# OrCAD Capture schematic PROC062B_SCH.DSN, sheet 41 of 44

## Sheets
41 41. SoC POWER SUPPLY: size C; title: SoC POWER SUPPLY
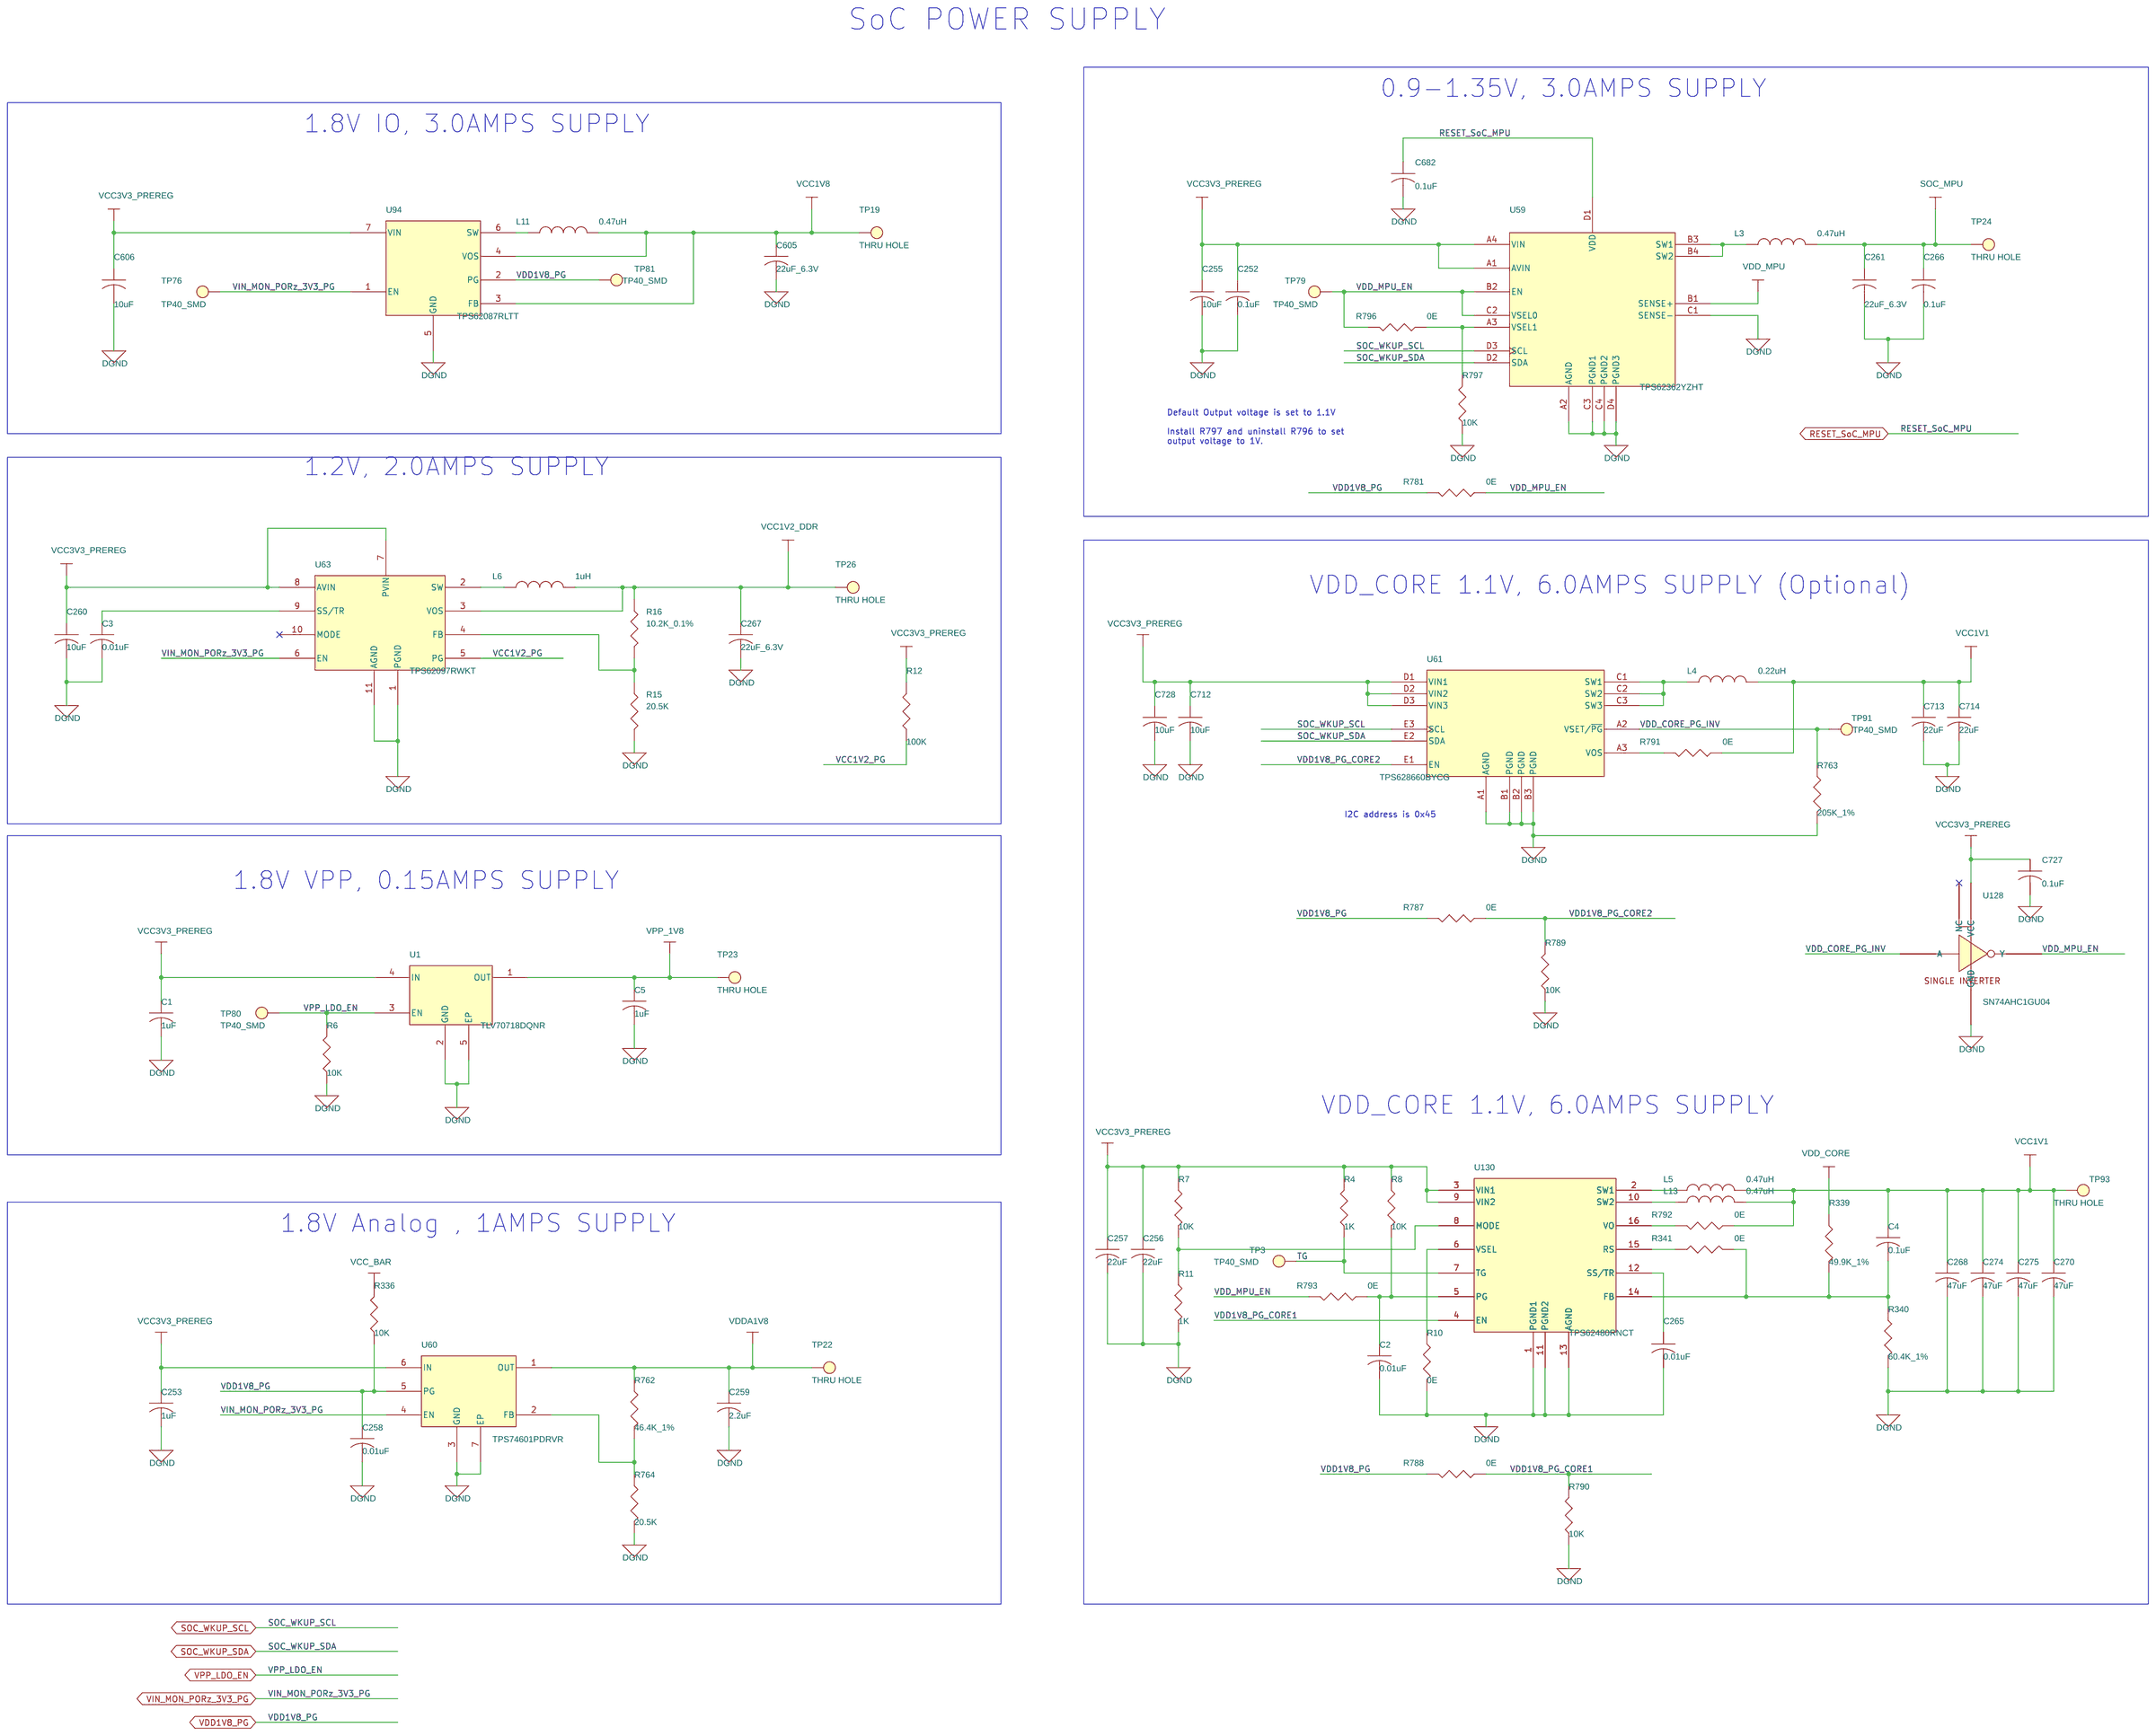
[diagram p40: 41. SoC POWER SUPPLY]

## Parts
C1  1uF  [CAP0603_1]
C2  0.01uF  [CAP0201_0-5]
C3  0.01uF  [CAP0201_0-5]
C4  0.1uF  [CAP0201_0-5]
C5  1uF  [CAP0603_1]
C252  0.1uF  [CAP0201_0-5]
C253  1uF  [CAP0603_1]
C255  10uF  [CAP1206_2]
C256  22uF  [CAP1206_2]
C257  22uF  [CAP1206_2]
C258  0.01uF  [CAP0201_0-5]
C259  2.2uF  [CAP0402_0-75]
C260  10uF  [CAP0603_1]
C261  22uF_6.3V  [CAP0603]
C265  0.01uF  [CAP0402_0-75]
C266  0.1uF  [CAP0201_0-5]
C267  22uF_6.3V  [CAP0603]
C268  47uF  [CAP0603_1]
C270  47uF  [CAP0603_1]
C274  47uF  [CAP0603_1]
C275  47uF  [CAP0603_1]
C605  22uF_6.3V  [CAP0603]
C606  10uF  [CAP1206_2]
C682  0.1uF  [CAP0201_0-5]
C712  10uF  [CAP0603_1]
C713  22uF  [CAP1206_2]
C714  22uF  [CAP1206_2]
C727  0.1uF  [CAP0201_0-5]
C728  10uF  [CAP0603_1]
L3  0.47uH  [IND_XEL4030_170X170_SMD_1-6]
L4  0.22uH  [IND_XAL4020_170X170_SMD_2-1]
L5  0.47uH  [IND_XEL4030_170X170_SMD_1-6]
L6  1uH  [IND_IHLP2020AB_210X210_SMD_1-2]
L11  0.47uH  [IND_XEL4030_170X170_SMD_1-6]
L13  0.47uH  [IND_XEL4030_170X170_SMD_1-6]
R4  1K  [RES0201]
R6  10K  [RES0402_0-5]
R7  10K  [RES0402_0-5]
R8  10K  [RES0402_0-5]
R10  0E  [RES0402_0-5]
R11  1K  [RES0201]
R12  100K  [RES0402_0-5]
R15  20.5K  [RES0402]
R16  10.2K_0.1%  [RES0402]
R336  10K  [RES0402_0-5]
R339  49.9K_1%  [RES0402]
R340  60.4K_1%  [RES0402_0-5]
R341  0E  [RES0402_0-5]
R762  46.4K_1%  [RES0402]
R763  205K_1%  [RES0402_0-5]
R764  20.5K  [RES0402]
R781  0E  [RES0402_0-5]
R787  0E  [RES0402_0-5]
R788  0E  [RES0402_0-5]
R789  10K  [RES0402_0-5]
R790  10K  [RES0402_0-5]
R791  0E  [RES0402_0-5]
R792  0E  [RES0402_0-5]
R793  0E  [RES0402_0-5]
R796  0E  [RES0402_0-5]
R797  10K  [RES0402_0-5]
TP3  TP40_SMD  [TP40_SMD]
TP19  THRU HOLE  [TP_40X65]
TP22  THRU HOLE  [TP_40X65]
TP23  THRU HOLE  [TP_40X65]
TP24  THRU HOLE  [TP_40X65]
TP26  THRU HOLE  [TP_40X65]
TP76  TP40_SMD  [TP40_SMD]
TP79  TP40_SMD  [TP40_SMD]
TP80  TP40_SMD  [TP40_SMD]
TP81  TP40_SMD  [TP40_SMD]
TP91  TP40_SMD  [TP40_SMD]
TP93  THRU HOLE  [TP_40X65]
U1  TLV70718DQNR  [X2SON4_TLV71318P_40X40_0-4]
U59  TPS62362YZHT  [DSBGA16_19-68_80X80_0-7]
U60  TPS74601PDRVR  [SON6_25-59_85X85_0-8]
U61  TPS628660BYCG  [WCSP15_13-77_40X70_0-5]
U63  TPS62097RWKT  [VQFNHR11_TPS62097_80X80_1]
U94  TPS62087RLTT  [VSONHR7_TPS62085_80X80_1]
U128  SN74AHC1GU04  [SOT23-5]
U130  TPS62480RNCT  [VQFNHR16_TPS62480_100X120_1]

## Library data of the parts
C1 C5 C253 = CAP: CAP CERAMIC 1uF 25V 10% X5R 0603; Chkd/date: MANIRAJA/230118; Crtd /date: MANIRAJA/230118; Custom_Duty: 15%; Customs_HS_Code: 85322990; Distributor_name: DIGIKEY; Distributor_part_number: 478-5142-1-ND; Height: 0.94MM; Mfr_name: AVX CORPORATION; Mfr_part_number: 06033D105KAT2A; Mistral Part No: 120010080040-R; Package: 0603; Part_type: CAPACITORS\CERAMIC; Project: TI_MAXIE_CPB; RoHS: RoHS; Temperature: -55°C+85°C; Tolerance: 10%; Voltage: 25V; Wattage: NA; Weight: 2mg; Datasheet: Y:\MIS_DATABASE\DATASHEETS\CAPACITORS\AVX_MLC.PDF
C2 C3 C258 = CAP: CAP CERAMIC 0.01uF 25V 10% X5R 0201; Chkd/date: MANIRAJA/230118; Crtd /date: MANIRAJA/230118; Custom_Duty: 15%; Customs_HS_Code: 85322990; Distributor_name: DIGIKEY; Distributor_part_number: GRM033R61E103KA12J-ND; Height: 0.33MM; Mfr_name: MURATA; Mfr_part_number: GRM033R61E103KA12J; Mistral Part No: 120018010007-R; Package: 0201; Part_type: CAPACITORS\CERAMIC; Project: TI_MAXIE_CPB; RoHS: RoHS; Temperature: -55°C+85°C; Tolerance: 10%; Voltage: 25V; Wattage: NA; Weight: 0.33mg; Datasheet: Y:\MIS_DATABASE\DATASHEETS\CAPACITORS\GRM033R61E103KA12.PDF
C4 C252 C266 C682 C727 = CAP: CAP CERAMIC 0.1uF 16V 10% X5R 0201; Chkd/date: MANIRAJA/120218; Crtd /date: MANIRAJA/120218; Custom_Duty: 15%; Customs_HS_Code: 85322990; Distributor_name: DIGIKEY; Distributor_part_number: 490-16742-1-ND; Height: 0.33MM; Mfr_name: MURATA; Mfr_part_number: GRM033R61C104KE84J; Mistral Part No: 120009030072-R; Package: 0201; Part_type: CAPACITORS\CERAMIC; Project: TI_MAXIE_CPB; RoHS: RoHS; Temperature: -55°C+85°C; Tolerance: 10%; Voltage: 16V; Wattage: NA; Weight: 0.33mg; Datasheet: Y:\MIS_DATABASE\DATASHEETS\CAPACITORS\GRM033R61C104KE84.PDF
C255 = CAP: CAP CERAMIC 10uF 50V 10% X5R 1206; Chkd/date: VASANTHA/190814; Crtd /date: BAVISH/230611; Custom_Duty: 15%; Customs_HS_Code: 85322990; Distributor_name: DIGIKEY; Distributor_part_number: 445-5998-1-ND; Footprint Path: Y:\MIS_DATABASE\Library\ALTIUM_TOOL\PCB_FOOTPRINTS\Altium_Footprint_Lib.PcbLib; Height: 1.90MM; Library Path: Y:\MIS_DATABASE\Library\ALTIUM_TOOL\SCHEMATICS_PARTS\MS_DISCRETE_Library.schlib; Mfr_name: TDK CORPORATION; Mfr_part_number: C3216X5R1H106K160AB; Mistral Part No: 120016030005-R; Package: 1206; Part_type: CAPACITORS\CERAMIC; Project: ITS-SINGAL_COND_CARD; RoHS: RoHS; Temperature: -55°C+85°C; Tolerance: 10%; Voltage: 50V; Wattage: NA; Weight: 16.2mg; Datasheet: Y:\MIS_DATABASE\DATASHEETS\CAPACITORS\TDK_C-SER-JUL17.PDF
C256 C257 C713 C714 = CAP: CAP CERAMIC 22uF 16V 20% X7R 1206; Chkd/date: VASANTHA/170117; Crtd /date: VASANTHA/170117; Custom_Duty: 15%; Customs_HS_Code: 85322990; Distributor_name: DIGIKEY; Distributor_part_number: 587-4319-1-ND; Height: 1.90MM; Mfr_name: TAIYO YUDEN; Mfr_part_number: EMK316BB7226ML-T; Mistral Part No: 120017010003-R; Package: 1206; Part_type: CAPACITORS\CERAMIC; Project: TRMM_SMART-M_PS; RoHS: RoHS; Temperature: -55°C+125°C; Tolerance: 20%; Voltage: 16V; Wattage: NA; Weight: 16.2mg; Datasheet: Y:\MIS_DATABASE\DATASHEETS\CAPACITORS\EMK316BB7226ML.PDF
C259 = CAP: CAP CERAMIC 2.2uF 10V 20% X5R 0402; Chkd/date: MANIRAJA/240118; Crtd /date: MANIRAJA/240118; Custom_Duty: 15%; Customs_HS_Code: 85322990; Distributor_name: DIGIKEY; Distributor_part_number: 490-12254-1-ND; Height: 0.55MM; Mfr_name: MURATA; Mfr_part_number: GRT155R61A225ME01D; Mistral Part No: 120018010016-R; Package: 0402; Part_type: CAPACITORS\CERAMIC; Project: TI_MAXIE_CPB; RoHS: RoHS; Temperature: -55°C+85°C; Tolerance: 20%; Voltage: 10V; Wattage: NA; Weight: 0.65mg; Datasheet: Y:\MIS_DATABASE\DATASHEETS\CAPACITORS\GRT155R61A225ME01.PDF
C260 C712 C728 = CAP: CAP CERAMIC 10uF 10V 10% X5R 0603; Chkd/date: MANIRAJA/230118; Crtd /date: MANIRAJA/230118; Custom_Duty: 15%; Customs_HS_Code: 85322990; Distributor_name: DIGIKEY; Distributor_part_number: 478-10766-1-ND; Height: 0.94MM; Mfr_name: AVX CORPORATION; Mfr_part_number: 0603ZD106KAT2A; Mistral Part No: 120010080001-R; Package: 0603; Part_type: CAPACITORS\CERAMIC; Project: TI_MAXIE_CPB; RoHS: RoHS; Temperature: -55°C+85°C; Tolerance: 10%; Voltage: 10V; Wattage: NA; Weight: 2mg; Datasheet: Y:\MIS_DATABASE\DATASHEETS\CAPACITORS\AVX_MLC.PDF
C261 C267 C605 = CAP: CAP CERAMIC 22uF 6.3V 20% X5R 0603; Alternate_mfr_name_A: YAGEO AMERICA; Alternate_mfr_part_number_A: CC0603MRX5R5BB226; Chkd/date: JEBRAN/090915; Crtd /date: JEBRAN/090915; Custom_Duty: 15%; Customs_HS_Code: 85322990; Distributor_name: DIGIKEY; Distributor_name_A: DIGIKEY; Distributor_part_number: 490-7611-2-ND; Distributor_part_number_A: 311-1815-1-ND; Height: 1.00MM; Mfr_name: MURATA; Mfr_part_number: GRM188R60J226MEA0; Mistral Part No: 120015090007-R; Package: 0603; Part_type: CAPACITORS\CERAMIC; Project: OCTBTS_3000; RoHS: RoHS; Temperature: -55°C+85°C; Tolerance: 20%; Voltage: 6.3V; Wattage: NA; Weight: NA; Datasheet: Y:\MIS_DATABASE\DATASHEETS\CAPACITORS\GRM188SERIES.PDF
C265 = CAP: CAP CERAMIC 0.01uF 10V 10% X7R 0402; Chkd/date: VASANTHA/061216; Crtd /date: MAZHAR/201005; Custom_Duty: 15%; Customs_HS_Code: 85322990; Distributor_name: DIGIKEY; Distributor_part_number: 478-7890-1-ND; Height: 0.56MM; Mfr_name: AVX CORPORATION; Mfr_part_number: 0402ZC103KAT2A; Mistral Part No: 120009030017-R; Package: 0402; Part_type: CAPACITORS\CERAMIC; Project: ADR; RoHS: RoHS; Temperature: -55°C+125°C; Tolerance: 10%; Voltage: 10V; Wattage: NA; Weight: 0.65mg; Datasheet: Y:\MIS_DATABASE\DATASHEETS\CAPACITORS\AVX_MLC.PDF
C268 C270 C274 C275 = CAP: CAP CERAMIC 47uF 6.3V 20% X5R 0603; Chkd/date: VASANTHA/211116; Crtd /date: MANIRAJA/211116; Custom_Duty: 15%; Customs_HS_Code: 85322990; Distributor_name: DIGIKEY; Distributor_part_number: 490-13247-1-ND; Height: 0.90MM; Mfr_name: MURATA; Mfr_part_number: GRM188R60J476ME15D; Mistral Part No: 120016110001-R; Package: 0603; Part_type: CAPACITORS\CERAMIC; Project: DLRL_3U_ESM_VPX; RoHS: RoHS; Temperature: -55°C+85°C; Tolerance: 20%; Voltage: 6.3V; Wattage: NA; Weight: 9.10mg; Datasheet: Y:\MIS_DATABASE\DATASHEETS\CAPACITORS\GRM188SERIES.PDF
C606 = CAP: CAP CERAMIC 10uF 16V 10% X7R 1206; Chkd/date: VASANTHA/291216; Crtd /date: MAZHAR/120909; Custom_Duty: 15%; Customs_HS_Code: 85322990; Distributor_name: DIGIKEY; Distributor_part_number: 399-3525-1-ND; Height: 1.80MM; Mfr_name: KEMET; Mfr_part_number: C1206C106K4RACTU; Mistral Part No: 120009090010-R; Package: 1206; Part_type: CAPACITORS\CERAMIC; Project: ADE POWER SUPPLY; RoHS: RoHS; Temperature: -55°C+125°C; Tolerance: 10%; Voltage: 16V; Wattage: NA; Weight: 16.2mg; Datasheet: Y:\MIS_DATABASE\DATASHEETS\CAPACITORS\KEMET-C08_X.PDF
L3 L5 L11 L13 = INDUCTOR: IND POWER 0.47uH 20% 11.2A SMD; Chkd/date: MANIRAJA/150218; Crtd /date: ALVY/150218; Custom_Duty: 24%; Customs_HS_Code: 85437099; Distributor_name: MOUSER; Distributor_part_number: 994-XFL4015-471MEB; Footprint Path: Y:\MIS_DATABASE\Library\ALTIUM_TOOL\PCB_FOOTPRINTS\Altium_Footprint_Lib.PcbLib; Height: 1.60MM; Library Path: Y:\MIS_DATABASE\Library\ALTIUM_TOOL\SCHEMATICS_PARTS\MS_DISCRETE_Library.schlib; Mfr_name: COILCRAFT; Mfr_part_number: XFL4015-471MEB; Mistral Part No: 130018020040-R; Package: SMD; Project: TI_MAXIE_CPB; RoHS: RoHS; Temperature: -40°C+125°C; Tolerance: 20%; Voltage: NA; Wattage: NA; Weight: 95mg; Datasheet: Y:\MIS_DATABASE\DATASHEETS\DISCRETES\INDUCTORS\XFL4015.PDF
L4 = INDUCTOR: IND POWER 0.22uH 16.8A 20% SMD; Chkd/date: MANIRAJA/100619; Crtd /date: MANIRAJA/100619; Custom_Duty: 24%; Customs_HS_Code: 85437099; Distributor_name: MOUSER; Distributor_part_number: 994-XAL4020-221MEB; Footprint Path: Y:\MIS_DATABASE\Library\ALTIUM_TOOL\PCB_FOOTPRINTS\Altium_Footprint_Lib.PcbLib; Height: 2.10MM; Library Path: Y:\MIS_DATABASE\Library\ALTIUM_TOOL\SCHEMATICS_PARTS\MS_DISCRETE_Library.schlib; Mfr_name: COILCARFT; Mfr_part_number: XAL4020-221MEB; Mistral Part No: 130019060012-R; Package: SMD; Project: TI_MAXIE_CPB; RoHS: RoHS; Temperature: -40°C+125°C; Tolerance: 20%; Voltage: NA; Wattage: NA; Weight: 180mg; Datasheet: Y:\MIS_DATABASE\DATASHEETS\DISCRETES\INDUCTORS\XAL40XX.PDF
L6 = INDUCTOR: IND POWER 1uH 4.4A 20% SMD; Chkd/date: VASANTHA/170317; Crtd /date: MANIRAJA/160317; Custom_Duty: 24%; Customs_HS_Code: 85437099; Distributor_name: DIGIKEY; Distributor_part_number: 541-1704-1-ND; Height: 1.20MM; Mfr_name: VISHAY; Mfr_part_number: IHLP2020ABER1R0M01; Mistral Part No: 130017030015-R; Package: SMD; Project: ADA_3U_FMC; RoHS: RoHS; Temperature: -55°C+125°C; Tolerance: 20%; Voltage: NA; Wattage: NA; Weight: 200mg; Datasheet: Y:\MIS_DATABASE\DATASHEETS\DISCRETES\INDUCTORS\IHLP2020AB.PDF
R4 R11 = RESISTOR: RES 1K 1/20W 5% 0201; Chkd/date: JEBRAN/110815; Crtd /date: JEBRAN/110815; Custom_Duty: 15%; Customs_HS_Code: 85332119; Distributor_name: DIGIKEY; Distributor_part_number: 541-1.00KAABCT-ND; Height: 0.28MM; Mfr_name: VISHAY; Mfr_part_number: CRCW02011K00FKED; Mistral Part No: 110015080014-R; Package: 0201; Part_type: RESISTORS\FIXED; Project: OCTASIC_3000; RoHS: RoHS; Temperature: -55°C+155°C; Tolerance: 5%; Voltage: NA; Wattage: 1/20W; Weight: NA; Datasheet: Y:\MIS_DATABASE\DATASHEETS\RESISTORS\CRCW0201.PDF
R6-R8 R336 R789 R790 R797 = RESISTOR: RES 10K 1/16W 5% 0402; Chkd/date: VASANTHA/061216; Crtd /date: MAZHAR/230805; Custom_Duty: 15%; Customs_HS_Code: 85332119; Distributor_name: DIGIKEY; Distributor_part_number: 311-10KJRCT-ND; Footprint Path: Y:\MIS_DATABASE\Library\ALTIUM_TOOL\PCB_FOOTPRINTS\Altium_Footprint_Lib.PcbLib; Height: 0.40MM; Library Path: Y:\MIS_DATABASE\Library\ALTIUM_TOOL\SCHEMATICS_PARTS\MS_DISCRETE_Library.schlib; Mfr_name: YAGEO AMERICA; Mfr_part_number: RC0402JR-0710KL; Mistral Part No: 110009030208-R; Package: 0402; Part_type: RESISTORS\FIXED; Project: HSE; RoHS: Pb-Free; Temperature: -55°C+155°C; Tolerance: 5%; Voltage: NA; Wattage: 1/16W; Weight: 0.65mg; Datasheet: Y:\MIS_DATABASE\DATASHEETS\RESISTORS\YAGEO-RC0402.PDF
R10 R341 R781 R787 R788 R791-R793 R796 = RESISTOR: RES 0E 1/16W 0402; Chkd/date: VASANTHA/201216; Crtd /date: MUDDU/190810; Custom_Duty: 15%; Customs_HS_Code: 85332119; Distributor_name: DIGIKEY; Distributor_part_number: 541-0.0JCT-ND; Footprint Path: Y:\MIS_DATABASE\Library\ALTIUM_TOOL\PCB_FOOTPRINTS\Altium_Footprint_Lib.PcbLib; Height: 0.40MM; Library Path: Y:\MIS_DATABASE\Library\ALTIUM_TOOL\SCHEMATICS_PARTS\MS_DISCRETE_Library.schlib; Mfr_name: VISHAY; Mfr_part_number: CRCW04020000Z0ED; Mistral Part No: 110010080019-P; Package: 0402; Part_type: RESISTORS\FIXED; Project: PB_BUGBASE; RoHS: Pb-Free; Temperature: -55°C+155°C; Tolerance: NA; Voltage: NA; Wattage: 1/16W; Weight: 0.65g/1000pcs; Datasheet: Y:\MIS_DATABASE\DATASHEETS\RESISTORS\CRCW0603.PDF
R12 = RESISTOR: RES 100K 1/16W 5% 0402; Chkd/date: VASANTHA/061216; Crtd /date: BAVISH/010611; Custom_Duty: 15%; Customs_HS_Code: 85332119; Distributor_name: DIGIKEY; Distributor_part_number: 541-100KJCT-ND; Height: 0.40MM; Mfr_name: VISHAY; Mfr_part_number: CRCW0402100KJNED; Mistral Part No: 110011060002-R; Package: 0402; Part_type: RESISTORS\FIXED; Project: AM4515_EVM_LCD; RoHS: RoHS; Temperature: -55°C+155°C; Tolerance: 5%; Voltage: NA; Wattage: 1/16W; Weight: 0.65mg; Datasheet: Y:\MIS_DATABASE\DATASHEETS\RESISTORS\CRCW0603.PDF
R15 R764 = RESISTOR: RES 20.5K 1/10W 1% 0402; Chkd/date: MAZHAR/0141010; Crtd /date: BAVISH/290910; Custom_Duty: 15%; Customs_HS_Code: 85332119; Distributor_name: DIGIKEY; Distributor_part_number: P20.5KLCT-ND; Footprint Path: Y:\MIS_DATABASE\Library\ALTIUM_TOOL\PCB_FOOTPRINTS\Altium_Footprint_Lib.PcbLib; Height: 0.40MM; Library Path: Y:\MIS_DATABASE\Library\ALTIUM_TOOL\SCHEMATICS_PARTS\MS_DISCRETE_Library.schlib; Mfr_name: PANASONIC-ECG; Mfr_part_number: ERJ-2RKF2052X; Mistral Part No: 110010090063-R; Package: 0402; Part_type: RESISTORS\FIXED; Project: ITS; RoHS: RoHS; Temperature: -55°C+125°C; Tolerance: 1%; Wattage: 1/10W; Weight: 0.8/1000g; Datasheet: Y:\MIS_DATABASE\DATASHEETS\RESISTORS\ERJ2R.PDF
R16 = RESISTOR: RES 10.2K 1/16W 0.1% 0402; Chkd/date: MAZHAR/200611; Crtd /date: BAVISH/240511; Custom_Duty: 15%; Customs_HS_Code: 85332119; Distributor_name: DIGIKEY; Distributor_part_number: TNP10.2KDACT-ND; Height: 0.40MM; Mfr_name: VISHAY; Mfr_part_number: TNPW040210K2BEED; Mistral Part No: 110011050017-R; Package: 0402; Part_type: RESISTORS\FIXED; Project: HMC; RoHS: RoHS; Temperature: -55°C+125°C; Tolerance: 0.1%; Voltage: NA; Wattage: 1/16W; Weight: 0.65/1000g; Datasheet: Y:\MIS_DATABASE\DATASHEETS\RESISTORS\VISHAY_TNPW.PDF
R339 = RESISTOR: RES 49.9K1/16W 1% 0402; Chkd/date: MAZHAR/220709; Crtd /date: GEETHA/090606; Custom_Duty: 15%; Customs_HS_Code: 85332119; Distributor_name: DIGIKEY; Distributor_part_number: 311-49.9KLRCT-ND; Height: 0.40MM; Mfr_name: YAGEO AMERICA; Mfr_part_number: RC0402FR-0749K9L; Mistral Part No: 110009030904-P; Package: 0402; Part_type: RESISTORS\FIXED; Project: PNAV; RoHS: Pb-Free; Tolerance: 1%; Wattage: 1/16W; Datasheet: Y:\MIS_DATABASE\DATASHEETS\RESISTORS\YAGEO-RC0402.PDF
R340 = RESISTOR: RES 60.4K 1/16W 1% 0402; Chkd/date: VASANTHA/281216; Crtd /date: USMAN/201112; Cust_part_number: 4700-80042E; Custom_Duty: 15%; Customs_HS_Code: 85332119; Distributor_name: DIGIKEY; Distributor_part_number: 311-60.4KLRCT-ND; Height: 0.40MM; Mfr_name: YAGEO AMERICA; Mfr_part_number: RC0402FR-0760K4L; Mistral Part No: 110012110012-R; Package: 0402; Part_type: RESISTORS\FIXED; Project: ITS-CONTROLER_CARD; RoHS: RoHS; Temperature: -55°C+155°C; Tolerance: 1%; Voltage: NA; Wattage: 1/16W; Weight: 0.65mg; Datasheet: Y:\MIS_DATABASE\DATASHEETS\RESISTORS\YAGEO-RC0402.PDF
R762 = RESISTOR: RES 46.4K 1/16W 1% 0402; Chkd/date: USMAN/230413; Crtd /date: USMAN/180213; Custom_Duty: 15%; Customs_HS_Code: 85332119; Distributor_name: DIGIKEY; Distributor_part_number: 541-46.4KLCT-ND; Footprint Path: Y:\MIS_DATABASE\Library\ALTIUM_TOOL\PCB_FOOTPRINTS\Altium_Footprint_Lib.PcbLib; Height: 0.40MM; Library Path: Y:\MIS_DATABASE\Library\ALTIUM_TOOL\SCHEMATICS_PARTS\MS_DISCRETE_Library.schlib; Mfr_name: VISHAY; Mfr_part_number: CRCW040246K4FKED; Mistral Part No: 110013020001-R; Package: 0402; Part_type: RESISTORS\FIXED; Project: ITS-SCP; RoHS: RoHS; Temperature: -55°C+155°C; Tolerance: 1%; Voltage: NA; Wattage: 1/16W; Weight: 0.65mg; Datasheet: Y:\MIS_DATABASE\DATASHEETS\RESISTORS\CRCW0603.PDF
R763 = RESISTOR: RES 205K 1/10W 1% 0402; Chkd/date: MAZHAR/110310; Crtd /date: MUDDU/080310; Custom_Duty: 15%; Customs_HS_Code: 85332119; Distributor_name: DIGIKEY; Distributor_part_number: P205KLCT-ND; Footprint Path: Y:\MIS_DATABASE\Library\ALTIUM_TOOL\PCB_FOOTPRINTS\Altium_Footprint_Lib.PcbLib; Height: 0.40MM; Library Path: Y:\MIS_DATABASE\Library\ALTIUM_TOOL\SCHEMATICS_PARTS\MS_DISCRETE_Library.schlib; Mfr_name: PANASONIC-ECG; Mfr_part_number: ERJ-2RKF2053X; Mistral Part No: 110010030029-R; Package: 0402; Part_type: RESISTORS\FIXED; Project: VME_DSP_SUITE; RoHS: RoHS; Temperature: -55°C+155°C; Tolerance: 1%; Voltage: NA; Wattage: 1/10W; Weight: 0.8mg; Datasheet: Y:\MIS_DATABASE\DATASHEETS\RESISTORS\PAN-ERJSER_NOV17.PDF
TP3 TP76 TP79-TP81 TP91 = TESTPOINT: TESTPOINT CIR 40 SMD; Chkd/date: MAZHAR/190505; Crtd /date: MAZHAR/190505; Distributor_name: NA; Distributor_part_number: NA; Footprint Path: Y:\MIS_DATABASE\Library\ALTIUM_TOOL\PCB_FOOTPRINTS\Altium_Footprint_Lib.PcbLib; Height: NA; Library Path: Y:\MIS_DATABASE\Library\ALTIUM_TOOL\SCHEMATICS_PARTS\MS_DISCRETE_Library.schlib; MECHANICAL 3D STEP FILE: NA; Mfr_name: LOCAL; Mistral Part No: 130009030933; Package: SMD; Project: RAINIER-3; RoHS: NA; Temperature: NA; Tolerance: NA; Voltage: NA; Wattage: NA; Weight: NA; Datasheet: NA
TP19 TP22-TP24 TP26 TP93 = TESTPOINT: TESTPOINT 1.0MM DRILL PTH; Chkd/date: MAZHAR/271211; Crtd /date: SHREESHAIL/041005; Distributor_name: NA; Distributor_part_number: NA; Height: NA; Mfr_name: LOCAL; Mistral Part No: 130009030938; Package: THRU-HOLE; Part_type: MISC\TESTPOINT; Project: HSE; Datasheet: NA
U1 = TLV71318PDQNR_X2SON4: IC 200mA LOW IQ LOW NOISE LDO REGULATOR X2SON-4; Chkd/date: MANIRAJA/270218; Crtd /date: ALVY/260218; Custom_Duty: 15%; Customs_HS_Code: 85423100; Distributor_name: DIGIKEY; Distributor_part_number: 296-36768-1-ND; Footprint Path: Y:\MIS_DATABASE\Library\ALTIUM_TOOL\PCB_FOOTPRINTS\Altium_Footprint_Lib.PcbLib; Height: 0.40MM; Library Path: Y:\MIS_DATABASE\Library\ALTIUM_TOOL\SCHEMATICS_PARTS\MS_MISCPOWER_Library.schlib; Mfr_name: TEXAS INSTRUMENTS; Mistral Part No: 142018020038-R; Package: X2SON-4; Part_type: ICS\POWER\VOLTAGE REGULATOR; Project: TI_MAXIE_CPB; RoHS: RoHS; Temperature: -40°C+125°C; Tolerance: NA; Voltage: NA; Wattage: NA; Weight: 1.5mg; Datasheet: Y:\MIS_DATABASE\DATASHEETS\ICS\POWER\TLV707X.PDF
U59 = TPS6236X_DSBGA16: IC 3A PROCESSOR SUPPLY WITH I2C INTERFACE AND REMOTE SENSE DSBGA16; Chkd/date: MANIRAJA/090120; Crtd /date: ALVY/090120; Custom_Duty: 15%; Customs_HS_Code: 85423100; Distributor_name: DIGIKEY; Distributor_part_number: 296-TPS62362YZHTCT-ND; Footprint Path: Y:\MIS_DATABASE\Library\ALTIUM_TOOL\PCB_FOOTPRINTS\Altium_Footprint_Lib.PcbLib; Height: 0.63MM; Library Path: Y:\MIS_DATABASE\Library\ALTIUM_TOOL\SCHEMATICS_PARTS\MS_MISCPOWER_Library.schlib; Mfr_name: TEXAS INSTRUMENTS; Mistral Part No: 142020010003-R; Package: DSBGA16; Part_type: ICS\POWER\DC-DC CONVERTER; Project: TI_MAXIE_CPB; RoHS: RoHS; Temperature: -40°C+85°C; Tolerance: NA; Voltage: NA; Wattage: NA; Weight: 5.1mg; Datasheet: Y:\MIS_DATABASE\DATASHEETS\ICS\POWER\TPS6236XX.PDF
U60 = TPS74501_WSON6: IC 1A ADJ OUTPUT LDO WITH POWER-GOOD WSON6; Chkd/date: MANIRAJA/060619; Crtd /date: ALVY/060619; Custom_Duty: 15%; Customs_HS_Code: 85423100; Distributor_name: MOUSER; Distributor_part_number: 595-TPS74601PDRVR; Footprint Path: Y:\MIS_DATABASE\Library\ALTIUM_TOOL\PCB_FOOTPRINTS\Altium_Footprint_Lib.PcbLib; Height: 0.80MM; Library Path: Y:\MIS_DATABASE\Library\ALTIUM_TOOL\SCHEMATICS_PARTS\MS_MISCPOWER_Library.schlib; Mfr_name: TEXAS INSTRUMENTS; Mistral Part No: 142019060004-R; Package: WSON6; Part_type: ICS\POWER\VOLTAGE REGULATOR; Project: TI_MAXIE_CPB; RoHS: RoHS; Temperature: -40°C+125°C; Tolerance: NA; Voltage: NA; Wattage: NA; Weight: NA; Datasheet: Y:\MIS_DATABASE\DATASHEETS\ICS\POWER\TPS74601.PDF
U61 = TPS628660B_WCSP15: IC 2.4-5.5V I/P 6A O/P SYNC STEP DOWN CONVERTER WITH I2C INTERFACE WCSP15; Chkd/date: MANIRAJA/040619; Crtd /date: MANIRAJA/040619; Custom_Duty: 15%; Customs_HS_Code: 85423100; Distributor_name: NA; Distributor_part_number: NA; Footprint Path: Y:\MIS_DATABASE\Library\ALTIUM_TOOL\PCB_FOOTPRINTS\Altium_Footprint_Lib.PcbLib; Height: 0.50MM; Library Path: Y:\MIS_DATABASE\Library\ALTIUM_TOOL\SCHEMATICS_PARTS\MS_MISCPOWER_Library.schlib; Mfr_name: TEXAS INSTRUMENTS; Mistral Part No: 142019060001; Package: WCSP15; Part_type: ICS\POWER\CONVERTER; Project: TI_MAXIE_CPB; RoHS: NA; Temperature: NA; Tolerance: NA; Voltage: NA; Wattage: NA; Weight: NA; Datasheet: Y:\MIS_DATABASE\DATASHEETS\ICS\POWER\TPS62866.PDF
U63 = TPS62097RWKT_VQFNHR11: IC 2A SYNCHRONOUS STEP DOWN CONVERTER WITH IDCS CONTROL VQFN-HR11; Chkd/date: MANIRAJA/270917; Crtd /date: MANIRAJA/270917; Custom_Duty: 15%; Customs_HS_Code: 85423100; Distributor_name: DIGIKEY; Distributor_part_number: 296-43330-1-ND; Height: 1.00MM; Mfr_name: TEXAS INSTRUMENTS; Mistral Part No: 142017090025-R; Package: VQFN-HR11; Part_type: ICS\POWER\CONVERTER; Project: TI_MAXIE_CPB; RoHS: RoHS; Temperature: -40°C+125°C; Tolerance: NA; Voltage: NA; Wattage: NA; Weight: NA; Datasheet: Y:\MIS_DATABASE\DATASHEETS\ICS\POWER\TPS62097.PDF
U94 = TPS62085RLTR_VSONHR7: IC 3A 1.8V STEP DOWN CONVERTER WITH SHORT CIRCUIT PROTECTION VSON-HR7; Chkd/date: MANIRAJA/310818; Crtd /date: MANIRAJA/310818; Custom_Duty: 15%; Customs_HS_Code: 85423100; Distributor_name: DIGIKEY; Distributor_part_number: 296-37087-1-ND; Footprint Path: Y:\MIS_DATABASE\Library\ALTIUM_TOOL\PCB_FOOTPRINTS\Altium_Footprint_Lib.PcbLib; Height: 1.00MM; Library Path: Y:\MIS_DATABASE\Library\ALTIUM_TOOL\SCHEMATICS_PARTS\MS_MISCPOWER_Library.schlib; Mfr_name: TEXAS INSTRUMENTS; Mistral Part No: 142018080020-R; Package: VSON-HR7; Part_type: ICS\POWER\CONVERTER; Project: TI_MAXIE_CPB; RoHS: RoHS; Temperature: -40°C+125°C; Tolerance: NA; Voltage: NA; Wattage: NA; Weight: 8.8mg; Datasheet: Y:\MIS_DATABASE\DATASHEETS\ICS\POWER\TPS62085.PDF
U128 = SN74AHC1GU04DBVR_SOT23-5: IC SINGLE INVERTER GATE SOT23-5; Chkd/date: SHREESHAIL/120106; Crtd /date: MAZHAR/160805; Custom_Duty: 15%; Customs_HS_Code: 85423100; Distributor_name: DIGIKEY; Distributor_part_number: 296-1095-1-ND; Height: 1.45MM; Mfr_name: TEXAS INSTRUMENTS; Mfr_part_number: SN74AHC1GU04DBVR; Mistral Part No: 141009030206; Part_type: ICS\DIGITAL\GATES; Project: HSE; Datasheet: Y:\MIS_DATABASE\DATASHEETS\ICS\DIGITAL\GATES\SN74AHC1GU04.PDF
U130 = TPS62480RNCT_VQFNHR16: IC 2-PHASE STEP DOWN DC-DC CONVERTER VQFN-HR16; Chkd/date: MANIRAJA/220917; Crtd /date: MANIRAJA/220917; Custom_Duty: 15%; Customs_HS_Code: 85423100; Distributor_name: DIGIKEY; Distributor_part_number: 296-43867-1-ND; Height: 1.00MM; Mfr_name: TEXAS INSTRUMENTS; Mistral Part No: 142017090012-R; Package: VQFN-HR16; Part_type: ICS\POWER\DC-DC CONVERTER; Project: TI_MAXIE_CPB; RoHS: RoHS; Temperature: -40°C+125°C; Tolerance: NA; Voltage: NA; Wattage: NA; Weight: 46mg; Datasheet: Y:\MIS_DATABASE\DATASHEETS\ICS\POWER\TPS62480R.PDF

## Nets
DGND: C1.2 C2.2 C3.2 C5.2 C252.2 C253.2 C255.2 C256.2 C257.2 C258.2 C259.2 C260.2 C261.2 C265.2 C266.2 C267.2 C268.2 C270.2 C274.2 C275.2 C605.2 C606.2 C682.2 C712.2 C713.2 C714.2 C727.2 C728.2 R6.1 R10.2 R11.2 R15.2 R340.2 R763.2 R764.2 R789.1 R790.1 R797.1 U1.2(GND) U1.5(EP) U59.A2(AGND) U59.C1(SENSE-) U59.C3(PGND1) U59.C4(PGND2) U59.D4(PGND3) U60.3(GND) U60.7(EP) U61.A1(AGND) U61.B1(PGND) U61.B2(PGND) U61.B3(PGND) U63.1(PGND) U63.11(AGND) U94.5(GND) U128.3(GND) U130.1(PGND1) U130.11(PGND2) U130.13(AGND) ; also on sheet 11 12 13 14 15 16 17 18 19 20 21 22 23 24 25 26 27 28 29 30 31 32 33 34 35 36 37 38 39 40 42 43 44
VCC1V1: C4.1 C268.1 C270.1 C274.1 C275.1 C713.1 C714.1 L4.2 L5.2 L13.2 R791.1 R792.1 TP93.1(TP) ; also on sheet 26
VCC1V2_DDR: C267.1 L6.2 R16.1 TP26.1(TP) U63.3(VOS) ; also on sheet 26
VCC1V2_PG: R12.1 U63.5(PG)
VCC1V8: C605.1 L11.2 TP19.1(TP) U94.3(FB) U94.4(VOS) ; also on sheet 11 18 19 20 21 22 23 26 29 31 33 35 36 37 38 44
VCC3V3_IO: R336.2 ; also on sheet 11 18 19 20 21 22 23 24 25 26 28 29 30 31 33 34 35 36 37 38 39 42 43 44
VCC3V3_PREREG: C1.1 C252.1 C253.1 C255.1 C256.1 C257.1 C260.1 C606.1 C712.1 C727.1 C728.1 R4.2 R7.1 R8.1 R12.2 U1.4(IN) U59.A1(AVIN) U59.A4(VIN) U60.6(IN) U61.D1(VIN1) U61.D2(VIN2) U61.D3(VIN3) U63.7(PVIN) U63.8(AVIN) U94.7(VIN) U128.5(VCC) U130.3(VIN1) U130.9(VIN2) ; also on sheet 13 39 40 42
VDD1V8_PG: C258.1 R336.1 R781.2 R787.2 R788.2 TP81.1(TP) U60.5(PG) U94.2(PG) ; also on sheet 42
VDD1V8_PG_CORE1: R788.1 R790.2 U130.4(EN)
VDD1V8_PG_CORE2: R787.1 R789.2 U61.E1(EN)
VDD_CORE: R339.1 ; also on sheet 12 13 26 39
VDD_CORE_PG_INV: R763.1 TP91.1(TP) U61.A2(VSET/~{PG}) U128.2(A)
VDD_MPU: U59.B1(SENSE+) ; also on sheet 12 26 39
VDD_MPU_EN: R781.1 R793.2 R796.2 TP79.1(TP) U59.B2(EN) U59.C2(VSEL0) U128.4(Y)
VDDA1V8: C259.1 R762.1 TP22.1(TP) U60.1(OUT) ; also on sheet 26
VIN_MON_PORz_3V3_PG: TP76.1(TP) U60.4(EN) U63.6(EN) U94.1(EN) ; also on sheet 39 42
RESET_SoC_MPU: C682.1 U59.D1(VDD) ; also on sheet 37
SoC_MPU: C261.1 C266.1 L3.2 TP24.1(TP) ; also on sheet 26
SOC_WKUP_SCL: U59.D3(SCL) U61.E3(SCL) ; also on sheet 20 33 34 35 44
SOC_WKUP_SDA: U59.D2(SDA) U61.E2(SDA) ; also on sheet 20 33 34 35 44
TG: R4.1 TP3.1(TP) U130.7(TG)
VPP_1V8: C5.1 TP23.1(TP) U1.1(OUT) ; also on sheet 13
VPP_LDO_EN: R6.2 TP80.1(TP) U1.3(EN) ; also on sheet 19
N17781485: L11.1 U94.6(SW)
N17781689: L6.1 U63.2(SW)
N17781701: R15.1 R16.2 U63.4(FB)
N17781734: L3.1 U59.B3(SW1) U59.B4(SW2)
N18550089: C3.1 U63.9(SS/TR)
N23079966: R762.2 R764.1 U60.2(FB)
N23093100: L4.1 U61.C1(SW1) U61.C2(SW2) U61.C3(SW3)
N23956430: C265.1 U130.12(SS/TR)
N23956432: C4.2 R339.2 R340.1 R341.2 U130.14(FB)
N23956434: R10.1 U130.6(VSEL)
N23956518: C2.1 R8.2 R793.1 U130.5(PG)
N23956734: R7.2 R11.1 U130.8(MODE)
N23956742: L5.1 U130.2(SW1)
N23956744: L13.1 U130.10(SW2)
N23956762: R792.2 U130.16(VO)
N23956795: R341.1 U130.15(RS)
N24018720: R791.2 U61.A3(VOS)
N24303686: R796.1 R797.2 U59.A3(VSEL1)

Not connected (* = marked no-connect by the designer): U63 10(MODE)*; U128 1(NC)*

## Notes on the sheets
sheet 41
- SoC POWER SUPPLY
- 0.9-1.35V, 3.0AMPS SUPPLY
- 1.8V IO, 3.0AMPS SUPPLY
- Default Output voltage is set to 1.1V
  Install R797 and uninstall R796 to set
  output voltage to 1V.
- 1.2V, 2.0AMPS SUPPLY
- VDD_CORE 1.1V, 6.0AMPS SUPPLY (Optional)
- I2C address is 0x45
- 1.8V VPP, 0.15AMPS SUPPLY
- VDD_CORE 1.1V, 6.0AMPS SUPPLY
- 1.8V Analog , 1AMPS SUPPLY
